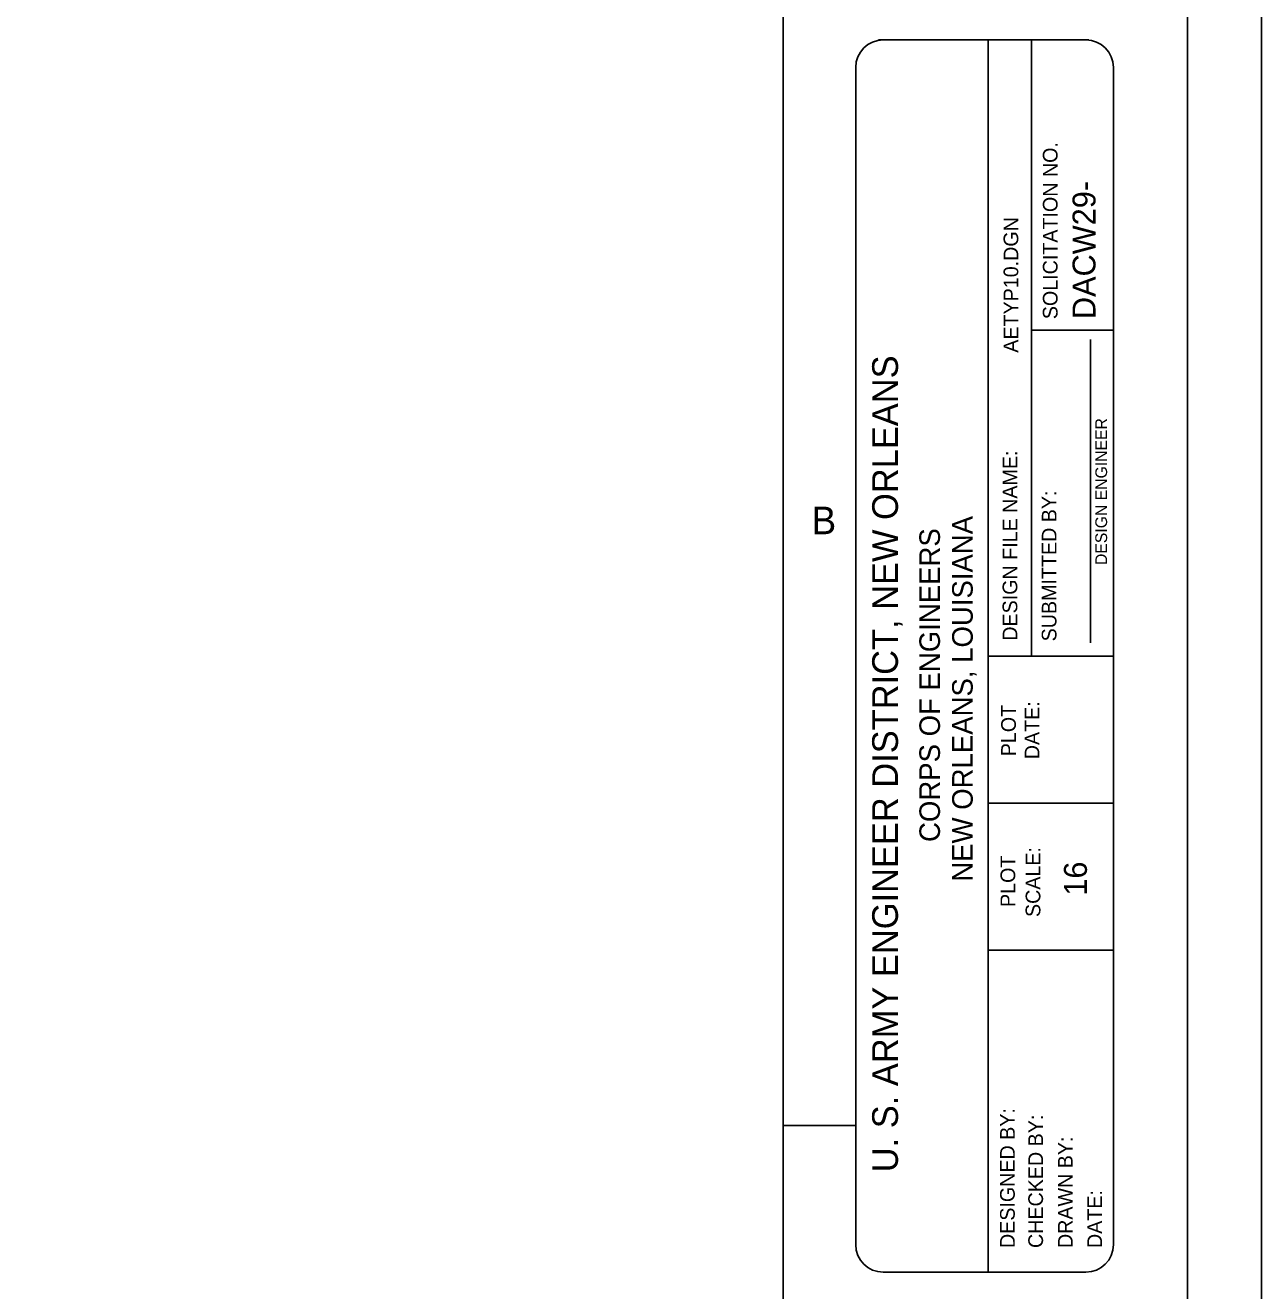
# Model space of a CAD drawing. Extents: x 22369.6 to 22428.3, y 22369.6 to 22415.
# Drawn here: x 22417.08 to 22428.29, y 22379.79 to 22391.26 of the extents above; entities that cross this region are included whole.
import ezdxf

# ---------------------------------------------------------------- set-up
doc = ezdxf.new("R2010")
doc.units = 0
for name, color, linetype in [('Level 1', 7, 'Continuous'), ('Level 10', 7, 'Continuous'), ('Level 2', 7, 'Continuous'), ('Level 7', 7, 'Continuous'), ('Level 9', 7, 'Continuous')]:
    doc.layers.add(name, color=color, linetype=linetype)

msp = doc.modelspace()

# ---------------------------------------------------------------- linework, layer by layer
at = {"layer": 'Level 1'}
for p, q in [((22426.72, 22391.125), (22424.816, 22391.125)), ((22425.808, 22391.125), (22425.808, 22379.957))]:
    msp.add_line(p, q, dxfattribs=at)
msp.add_lwpolyline([(22369.621, 22414.965), (22428.288, 22414.965), (22428.288, 22369.621), (22369.621, 22369.621)], close=True, dxfattribs=at)
for points in [[(22426.694, 22391.125), (22424.858, 22391.125)], [(22424.608, 22380.207), (22424.608, 22390.875)], [(22426.944, 22380.207), (22426.944, 22390.875)], [(22424.858, 22379.957), (22426.694, 22379.957)]]:
    msp.add_lwpolyline(points, dxfattribs=at)
for centre, start, end in [((22424.858, 22390.875), 90, 180), ((22426.694, 22390.875), 0, 90), ((22424.858, 22380.207), 180, 270), ((22426.694, 22380.207), 270, 0)]:
    msp.add_arc(centre, 0.25, start, end, dxfattribs=at)
at = {"layer": 'Level 10'}
msp.add_line((22423.952, 22381.285), (22424.608, 22381.285), dxfattribs=at)
at = {"layer": 'Level 2'}
for p, q in [((22426.202, 22391.125), (22426.202, 22385.541)), ((22426.944, 22388.496), (22426.202, 22388.496)), ((22426.736, 22385.662), (22426.736, 22388.411)), ((22426.944, 22385.541), (22425.808, 22385.541)), ((22426.944, 22384.208), (22425.808, 22384.208)), ((22426.944, 22382.875), (22425.808, 22382.875))]:
    msp.add_line(p, q, dxfattribs=at)
at = {"layer": 'Level 9'}
msp.add_line((22427.616, 22370.293), (22427.616, 22414.293), dxfattribs=at)
msp.add_lwpolyline([(22423.952, 22370.293), (22423.952, 22414.293)], dxfattribs=at)

# ---------------------------------------------------------------- texts
at = {"layer": 'Level 1'}
for s, height, p in [('SOLICITATION NO.', 0.13334, (22426.438, 22388.594)), ('AETYP10.DGN', 0.13334, (22426.082, 22388.29)), ('U. S. ARMY ENGINEER DISTRICT, NEW ORLEANS', 0.23333, (22424.991, 22380.863)), ('DESIGN ENGINEER', 0.10665, (22426.887, 22386.366)), ('DESIGN FILE NAME:', 0.13334, (22426.073, 22385.68)), ('SUBMITTED BY:', 0.13334, (22426.428, 22385.674)), ('PLOT', 0.1333, (22426.06, 22384.633)), ('DATE:', 0.1333, (22426.273, 22384.606)), ('PLOT', 0.1333, (22426.054, 22383.267)), ('SCALE:', 0.1333, (22426.282, 22383.176)), ('DESIGNED BY:', 0.13334, (22426.05, 22380.176)), ('CHECKED BY:', 0.13334, (22426.306, 22380.176)), ('DRAWN BY:', 0.1333, (22426.575, 22380.176)), ('DATE:', 0.1333, (22426.841, 22380.176))]:
    msp.add_text(s, height=height, rotation=90, dxfattribs=at).set_placement(p)
msp.add_text('B', height=0.25, dxfattribs=at).set_placement((22424.208, 22386.645))
at = {"layer": 'Level 7'}
for s, height, p in [('DACW29-', 0.208, (22426.782, 22388.595)), ('NEW ORLEANS, LOUISIANA', 0.18667, (22425.669, 22383.496)), ('CORPS OF ENGINEERS', 0.18667, (22425.372, 22383.856)), ('16', 0.208, (22426.704, 22383.369))]:
    msp.add_text(s, height=height, rotation=90, dxfattribs=at).set_placement(p)

doc.saveas('drawing.dxf')
